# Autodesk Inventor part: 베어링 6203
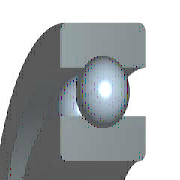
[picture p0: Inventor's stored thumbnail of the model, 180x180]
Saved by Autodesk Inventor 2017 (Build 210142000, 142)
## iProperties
IsCustomPart: 0
Created: 2016-05
Part Number: 베어링 6203
Material: 강철, 연강
Description: 깊은 그루브 볼 베어링
Document SubType Name: Modeling
Standard: KS B 2023
Designer: mduedu
Standards Organization: KS
Language: ko-KR
Size Designation: 6203 - 17 x 40 x 12
Categories: <MemberInstance><Categories><Category DisplayName="샤프트 부품" InternalName="7f7aeb1f-a693-4053-b835-cee3144e0d98" Mnemonic="SHFT"><Category DisplayName="베어링" Inter
Density: 1 g/cm^3
Appearance: 노란색
Author: mduedu
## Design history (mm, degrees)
sketch "스케치" dims "d0" = 5.98 (= -0.26 x WD + 0.26 x BD)
  geometry: L1 (3.01, 14.25)-(8.99, 14.25); L2 (6, 14.25)-(6, 11.26); L3 (6, 14.25)-(6, 17.24); L4 (3.778, 12.249)-(0, 12.249); L5 (0, 8.5)-(12, 8.5); L6 (3.778, 16.251)-(0, 16.251); L7 (0, 20)-(12, 20); L8 (12, 8.5)-(12, 12.249); L9 (8.222, 12.249)-(12, 12.249); L10 (8.222, 16.251)-(12, 16.251); L11 (12, 20)-(12, 16.251); L12 (-1.4, 0)-(8.4, 0) reference; L13 (0, -0.3)-(0, 5.3) reference
  constraints: 22 end point, 4 point on line, 2 collinear, 2 perpendicular, 2 symmetric about line, 1 midpoint, 1 parallel, 14 other
  dimensions: "d9" = 17 diameter of L5 L12 (= WD); "d11" = 40 diameter of L7 L12 (= BD); "d12" = 12 distance between parallel lines of L8 L13 (= KB); "d13" = 24.498 diameter of L9 L12 (= 0.326 x BD + 0.674 x WD)
revolve "본체" stored, may be unused: angle "d6" = 90 deg
revolve "볼" stored, may be unused: angle "d7" = 90 deg
pattern_circular "IDS_ARRAYBALL[SIMPL:T]" dims angle "d3" = 360 deg
body "Solid1"
fillet "모깎기1" dims "d1" = 0.6 (= KRS)
other parameters: "WD" = 17 [user parameter; used in 5 equation terms], "BD" = 40 [user parameter; used in 5 equation terms], "KB" = 12 [user parameter; used in 1 equation term], "KRS" = 0.6 [user parameter; used in 1 equation term], "d4" = 0, "d5" = 0, "d8" = 0, "d14" = 0, "d15" = 0, "BBA" = 0 [user parameter], "BC0" = 4750000 [user parameter], "BC" = 9560000 [user parameter], "WR" = 8.5 (= 0.5 x WD) [user parameter]
